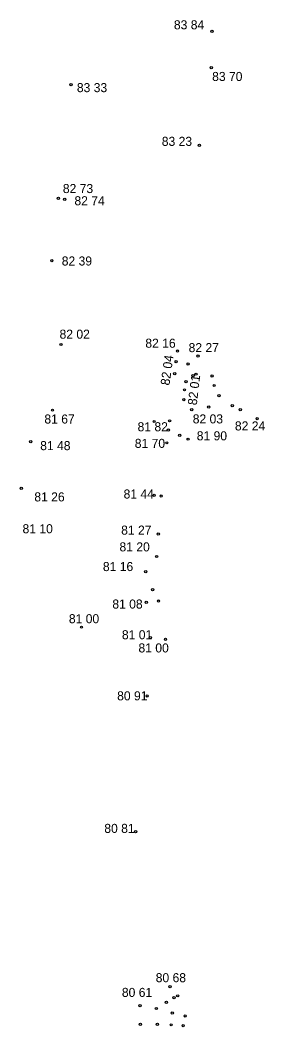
# Model space of a CAD drawing. Extents: x -602085 to -601979, y -1162698 to -1162507.
# Drawn here: x -602031 to -602020.19, y -1162649.75 to -1162605.3 of the extents above; entities that cross this region are included whole.
import ezdxf

# ---------------------------------------------------------------- set-up
doc = ezdxf.new("R2010")
doc.units = 0
doc.layers.add('Vrstva 58', color=7, linetype='Continuous')
doc.layers.add('Vrstva 60', color=7, linetype='Continuous')

msp = doc.modelspace()

# ---------------------------------------------------------------- linework, layer by layer
at = {"layer": 'Vrstva 60'}
for centre in [(-602022.53, -1162605.79), (-602022.56, -1162607.4), (-602028.75, -1162608.15), (-602023.08, -1162610.83), (-602029.31, -1162613.17), (-602029.03, -1162613.21), (-602029.6, -1162615.92), (-602029.2, -1162619.62), (-602024.05, -1162619.91), (-602023.14, -1162620.13), (-602024.11, -1162620.38), (-602023.58, -1162620.48), (-602024.17, -1162620.91), (-602023.36, -1162621), (-602023.23, -1162620.93), (-602022.52, -1162621.01), (-602023.67, -1162621.26), (-602022.43, -1162621.43), (-602023.74, -1162621.62), (-602022.22, -1162621.88), (-602023.77, -1162622.05), (-602021.63, -1162622.32), (-602029.57, -1162622.52), (-602023.42, -1162622.5), (-602022.67, -1162622.38), (-602021.28, -1162622.5), (-602025.08, -1162623.02), (-602024.4, -1162622.99), (-602020.53, -1162622.9), (-602024.45, -1162623.4), (-602023.95, -1162623.63), (-602030.53, -1162623.91), (-602024.52, -1162623.96), (-602023.58, -1162623.8), (-602030.95, -1162625.97), (-602025.08, -1162626.28), (-602024.77, -1162626.31), (-602024.9, -1162627.99), (-602024.97, -1162628.98), (-602025.45, -1162629.65), (-602025.15, -1162630.45), (-602025.43, -1162631.01), (-602024.89, -1162630.95), (-602028.29, -1162632.1), (-602025.25, -1162632.57), (-602024.58, -1162632.64), (-602025.39, -1162635.14), (-602025.9, -1162641.13), (-602024.38, -1162647.97), (-602024.2, -1162648.46), (-602024.04, -1162648.38), (-602025.7, -1162648.81), (-602024.98, -1162648.94), (-602024.54, -1162648.67), (-602024.28, -1162649.14), (-602023.71, -1162649.27), (-602025.69, -1162649.64), (-602024.94, -1162649.64), (-602024.33, -1162649.66), (-602023.8, -1162649.7)]:
    msp.add_circle(centre, 0.05, dxfattribs=at)

# ---------------------------------------------------------------- texts
at = {"layer": 'Vrstva 58'}
for s, p in [('83 84', (-602024.208, -1162605.703)), ('83 70', (-602022.52, -1162607.984)), ('83 33', (-602028.494, -1162608.477)), ('83 23', (-602024.744, -1162610.849)), ('82 73', (-602029.113, -1162612.932)), ('82 74', (-602028.602, -1162613.473)), ('82 39', (-602029.162, -1162616.132)), ('82 02', (-602029.259, -1162619.363)), ('82 16', (-602025.47, -1162619.762)), ('82 27', (-602023.559, -1162619.957)), ('81 67', (-602029.929, -1162623.11)), ('82 03', (-602023.377, -1162623.104)), ('81 82', (-602025.812, -1162623.452)), ('82 24', (-602021.514, -1162623.414)), ('81 90', (-602023.2, -1162623.851)), ('81 48', (-602030.114, -1162624.285)), ('81 70', (-602025.937, -1162624.185)), ('81 26', (-602030.373, -1162626.548)), ('81 44', (-602026.43, -1162626.421)), ('81 10', (-602030.894, -1162627.955)), ('81 27', (-602026.538, -1162628.016)), ('81 20', (-602026.612, -1162628.755)), ('81 16', (-602027.345, -1162629.624)), ('81 08', (-602026.927, -1162631.28)), ('81 00', (-602028.847, -1162631.927)), ('81 01', (-602026.504, -1162632.636)), ('81 00', (-602025.773, -1162633.218)), ('80 91', (-602026.715, -1162635.333)), ('80 81', (-602027.282, -1162641.186)), ('80 68', (-602025.012, -1162647.779)), ('80 61', (-602026.506, -1162648.428))]:
    msp.add_text(s, height=0.4, dxfattribs=at).set_placement(p)
for s, rotation, p in [('82 04', 82.1501, (-602024.406, -1162621.441)), ('82 01', 83.2573, (-602023.202, -1162622.317))]:
    msp.add_text(s, height=0.4, rotation=rotation, dxfattribs=at).set_placement(p)

doc.saveas('drawing.dxf')
